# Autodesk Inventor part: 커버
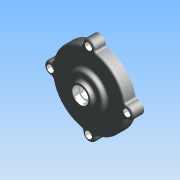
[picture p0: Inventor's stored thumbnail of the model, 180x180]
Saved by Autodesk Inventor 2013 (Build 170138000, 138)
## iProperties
Company: 한국ATC센터
Created: 2014-07
Part Number: 커버
Document SubType Name: 모델링
Designer: KYOUNG IL JANG
Material: 알루미늄 6061
Mass: 196.659 g
Surface Area: 278.607 cm^2
Volume: 72.5678 cm^3
Density: 2.71 g/cm^3
변환 표준: STEP AP214IS
파일 이름: C:\Users\SeoGD\Desktop\?쒗뿕\而ㅻ쾭-1.stp
전처리기: Build: 253, Release: 2010 SP1 - Date: Wed 07/29/2009
전송 단위: 밀리미터
불확실성: 0.01
Author: KYOUNG IL JANG
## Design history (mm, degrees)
revolve "회전1" stored, may be unused: angle "d27" = 90 deg
sketch "스케치2" dims "d29" = 104
  geometry: A1 r 8.5 centre (0, 52) between (8.074, 49.344) and (-8.074, 49.344); A2 r 50 centre (0, 0) between (-8.074, 49.344) and (8.074, 49.344) reference; 2 further points
  constraints: 4 point on circle, 2 vertical alignment, 1 centre point, 1 coincident, 2 other
  dimensions: "d28" = 17 diameter of A1
extrude "돌출1" join sketch "스케치2" stored distance "d30" = 10; taper "d31" = 0 deg
fillet "모깎기3" dims "d32" = 3
fillet "모깎기4" dims "d45" = 3, "d46" = 0.2
chamfer "모따기1" distance "d47" = 1; stored, may be unused: second distance "d48" = 2, angle "d49" = 45 deg
hole "구멍2" diameter "d38" = 5.5; stored, may be unused: countersink angle "d42" = 90 deg, drill point angle "d44" = 118 deg; dims "d36" = 10, "d37" = 10, "d39" = 6, "d40" = 9.5, "d41" = 5.4, "d43" = 8
node "솔리드1"
node "솔리드 본체"
node "곡면 본체"
pattern_circular "원형 패턴1" dims angle "d34" = 360 deg
pattern_circular "원형 패턴2" dims angle "d52" = 360 deg
sketch "스케치1"
  geometry: L1 (0, 0)-(0, 26); L2 (50, 0)-(50, 15); L3 (50, 15)-(25, 15); L4 (25, 15)-(25, 21); L5 (25, 21)-(15, 21); L6 (15, 21)-(13.66, 26); L7 (13.66, 26)-(10, 26); L8 (50, 0)-(45, 0); L9 (45, 0)-(45, 10); L10 (45, 10)-(14.5, 10); L11 (14.5, 10)-(13.266, 3); L12 (13.266, 3)-(11, 3); L13 (11, 3)-(11, 16); L14 (11, 16)-(7.5, 16); L15 (7.5, 16)-(7.5, 19); L16 (7.5, 19)-(10, 19); L17 (10, 19)-(10, 26)
  constraints: 34 end point, 10 parallel, 2 perpendicular, 2 point on line, 1 vertical
  dimensions: "d11" = 100 diameter of L2 L1; "d12" = 22 diameter of L13 L1; "d13" = 90 diameter of L9 L1; "d14" = 15 distance between parallel lines of L3 L8; "d15" = 10 distance between parallel lines of L8 L10; "d16" = 29 diameter of L10.end L1; "d17" = 100 deg angle of L11 L10; "d18" = 7 distance between parallel lines of L12 L10; "d19" = 13 distance between parallel lines of L14 L12; "d20" = 3 distance between parallel lines of L16 L14; "d21" = 15 diameter of L15 L1; "d22" = 20 diameter of L17 L1; "d23" = 30 diameter of L5.end L1; "d24" = 6 distance between parallel lines of L5 L3; "d25" = 50 diameter of L4 L1; "d26" = 105 deg angle of L5 L6; "d50" = 26 distance of L1.start L1.end
node "솔리드2"
